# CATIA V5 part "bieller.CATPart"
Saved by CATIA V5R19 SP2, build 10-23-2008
Part number: bieller
Bounding box of the stored display mesh (mm): x -11.25 to 162.5, y -5 to 15, z -30 to 30
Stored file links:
  C:\Users\marc\Desktop\boulot\Semestre 3\CFAO\Projet CFAO\robuste\bieller.CATPart
  C:\Users\marc\Desktop\boulot\Semestre 3\CFAO\Projet CFAO\robuste\vilbrequinr.CATPart
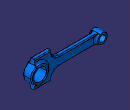
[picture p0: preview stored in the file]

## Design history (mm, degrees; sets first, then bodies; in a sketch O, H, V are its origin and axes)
Parameters
  longbielle = 150 mm
  demilarggdbielle = 30 mm
  demilargptbielle = 15 mm
  demiepbielle = 5 mm
  raygdtrou = 15 mm
  raypttrou = 7.5 mm
Body1 (main body)
  Sketch1 on zx-plane, origin (0, 0, 0), H (-1, 0, 0), V (0, 0, 1)
    point P1 (0, 0)
    line L1 (0, 0) -> (0, -10)
    line L2 (0, -10) -> (-93.75, -10)
    arc A1 centre (-93.75, -28.7891) radius 18.7891 from (-93.75, -10) to (-112.5, -30) ccw
    line L3 (-112.5, -30) -> (-150, -30)
    line L4 (-150, -30) -> (-150, 0)
    point P7 (-150, 0)
    line L5 (-150, 0) -> (0, 0)
    length L4 = 30 {= demilarggdbielle}
    length L5 = 150 {= longbielle}
    length L1 = 10 {= demilarggdbielle /3}
    length L3 = 37.5 {= longbielle /4}
    length L2 = 93.75 {= longbielle /1.6}
    distance P1 V = 0
    coincidence: P1 H, P7 H
    vertical: L1 V, L4 V
    horizontal: L2 H, L3 H, L5 H
    tangency: A1 L2
  Pad1: profile Sketch1, direction (0, 1, 0), length 5 {= demiepbielle}
  Mirror1: of the body so far, about xy-plane
  Sketch2 on face of Pad1, origin (0, 5, 0), H (-1, 0, 0), V (0, 0, 1)
    point P1 (-110, 0)
    coincidence: P1 H
  Sketch3 on face of Pad1, origin (0, 5, 0), H (-1, 0, 0), V (0, 0, 1)
    point P1 (-122.5, 0)
    circle A1 centre (-142.5, 0) radius 20
    point P2 (-142.5, 0)
    reference projected line E1 (-150, -30) -> (-150, 0) from edge [face of Pad1 | face of Pad1]
    radius A1 = 20 {= raygdtrou+(raygdtrou /3)}
    distance P2 E1 = 7.5 {= raygdtrou /2}
    coincidence: P1 H, A1 P1, P2 H
  Pad2: profile Sketch3, direction (0, -1, 0), length 10 {= demiepbielle *2}
  Sketch4 on end face of Pad2, origin (0, -5, 0), H (1, 0, 0), V (0, 0, 1)
    circle A1 centre (142.5, 0) radius 15
    point P1 (142.5, 0)
    reference projected circle E1 centre (142.5, 0) radius 20 from edge [end face of Pad2 | face of Pad2 from Sketch3.A1]
    radius A1 = 15 {= raygdtrou}
    coincidence: P1 H
    concentricity: A1 E1
  Pocket1: profile Sketch4, direction (0, 1, 0), length 600
  Sketch5 on face of Pad2, origin (0, 5, 0), H (-1, 0, 0), V (0, 0, 1)
    circle A1 centre (0, 0) radius 11.25
    radius A1 = 11.25 {= raypttrou +(raypttrou /2)}
  Pad3: profile Sketch5, direction (0, -1, 0), length 10 {= demiepbielle *2}
  Sketch6 on end face of Pad3, origin (0, -5, 0), H (1, 0, 0), V (0, 0, 1)
    circle A1 centre (0, 0) radius 7.5
    reference projected circle E1 centre (0, 0) radius 11.25 from edge [end face of Pad3 | face of Pad3 from Sketch5.A1]
    radius A1 = 7.5 {= raypttrou}
    concentricity: A1 E1
  Pocket2: profile Sketch6, direction (0, 1, 0), length 5000
  Fillet1: radius 5, on edge [face of Pad2 from Sketch3.A1 | face of Pad1]
  Fillet2: radius 5, on edge [face of Pad3 from Sketch5.A1 | face of Pad1]
  Fillet3: radius 2, on edge [face of Mirror1 | face of Pad1] (x3); edge [face of Pad1 | face of Pad1 from Sketch1.L2]; edge [face of Pad1 | face of Pad1 from Sketch1.A1]; edge [face of Pad1 | face of Pad1 from Sketch1.L3]
  Fillet4: radius 2, on edge [end face of Pad2 | face of Pad2 from Sketch3.A1]
  Mirror2: of the body so far, about face of Pad3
